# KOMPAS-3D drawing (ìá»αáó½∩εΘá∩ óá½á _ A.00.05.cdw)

Views: Спереди 1, Спереди, Проекционный вид 2, Изометрия XYZ 3, Изометрия XYZ
Referenced files in C:\Users\s.slezkin\Desktop\Раскатчик арок 2\: Направляющая вала _ A.00.05.m3d
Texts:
  Направляющая вала
  http://vk.com/sergey_krd
  Левая
  Сталь 40Х  ГОСТ 4543-71
Dimensions and other numbers on the sheet: 52; 12; 26; 18; 1:2; 1; 0,09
